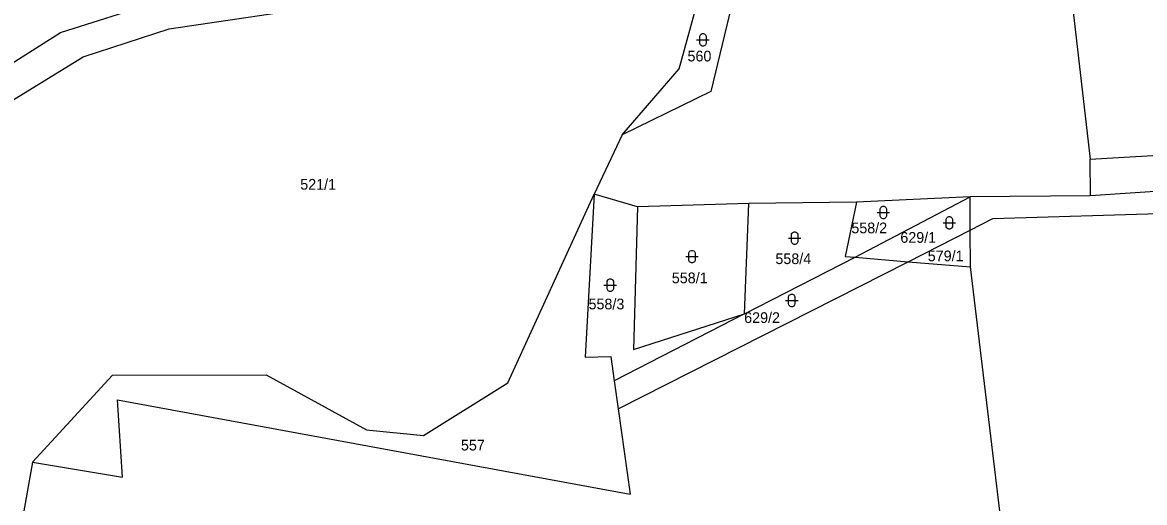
# Model space of a CAD drawing. Extents: x -794421 to -792735, y -1117671 to -1115559.
# Drawn here: x -793720 to -793541.7, y -1117244.8 to -1117168.6 of the extents above; entities that cross this region are included whole.
import ezdxf

# ---------------------------------------------------------------- set-up
doc = ezdxf.new("R2010")
doc.units = 0
for name, color, linetype in [('Vrstva 1', 7, 'Continuous'), ('Vrstva 14', 7, 'Continuous'), ('Vrstva 23', 7, 'Continuous')]:
    doc.layers.add(name, color=color, linetype=linetype)

msp = doc.modelspace()

# ---------------------------------------------------------------- linework, layer by layer
at = {"layer": 'Vrstva 1'}
for p, q in [((-793558.5, -1117120.1), (-793550.39, -1117190.25)), ((-793615.66, -1117175.93), (-793610.92, -1117158.67)), ((-793606.91, -1117164.01), (-793610.66, -1117179.49)), ((-793714, -1117170.15), (-793698.57, -1117165.26)), ((-793696.75, -1117169.55), (-793670.18, -1117165.64)), ((-793736.01, -1117184.09), (-793714, -1117170.15)), ((-793710.4, -1117173.99), (-793696.75, -1117169.55)), ((-793736.92, -1117190.31), (-793710.4, -1117173.99)), ((-793624.72, -1117186.38), (-793615.66, -1117175.93)), ((-793610.66, -1117179.49), (-793624.72, -1117186.38)), ((-793624.72, -1117186.38), (-793629.21, -1117195.83)), ((-793550.39, -1117190.25), (-793513.18, -1117188.14)), ((-793550.31, -1117196.07), (-793550.39, -1117190.25)), ((-793514.05, -1117193.72), (-793550.31, -1117196.07)), ((-793642.89, -1117225.74), (-793629.21, -1117195.83)), ((-793629.21, -1117195.83), (-793630.6, -1117221.67)), ((-793622.29, -1117197.82), (-793629.21, -1117195.83)), ((-793587.71, -1117205.83), (-793569.43, -1117196.25)), ((-793569.43, -1117196.25), (-793587.48, -1117197.06)), ((-793550.31, -1117196.07), (-793569.43, -1117196.25)), ((-793569.42, -1117201.52), (-793569.43, -1117196.25)), ((-793622.29, -1117197.82), (-793622.93, -1117220.47)), ((-793604.62, -1117197.29), (-793622.29, -1117197.82)), ((-793605.29, -1117214.83), (-793604.62, -1117197.29)), ((-793587.48, -1117197.06), (-793604.62, -1117197.29)), ((-793587.48, -1117197.06), (-793589.3, -1117205.7)), ((-793565.83, -1117199.7), (-793510.97, -1117198.02)), ((-793569.42, -1117201.52), (-793565.83, -1117199.7)), ((-793579.3, -1117206.53), (-793569.42, -1117201.52)), ((-793569.41, -1117207.36), (-793569.42, -1117201.52)), ((-793605.29, -1117214.83), (-793587.71, -1117205.83)), ((-793589.3, -1117205.7), (-793587.71, -1117205.83)), ((-793587.71, -1117205.83), (-793579.3, -1117206.53)), ((-793625.37, -1117229.91), (-793579.3, -1117206.53)), ((-793579.3, -1117206.53), (-793569.41, -1117207.36)), ((-793560.83, -1117278.35), (-793569.41, -1117207.36)), ((-793605.29, -1117214.83), (-793626.01, -1117225.43)), ((-793622.93, -1117220.47), (-793605.29, -1117214.83)), ((-793630.6, -1117221.67), (-793626.55, -1117221.59)), ((-793626.55, -1117221.59), (-793626.01, -1117225.43)), ((-793718.45, -1117238.37), (-793705.75, -1117224.56)), ((-793705.75, -1117224.56), (-793681.32, -1117224.51)), ((-793681.32, -1117224.51), (-793665.37, -1117233.24)), ((-793626.01, -1117225.43), (-793625.37, -1117229.91)), ((-793656.32, -1117234.1), (-793642.89, -1117225.74)), ((-793704.12, -1117240.73), (-793704.94, -1117228.48)), ((-793704.94, -1117228.48), (-793623.45, -1117243.42)), ((-793625.37, -1117229.91), (-793623.45, -1117243.42)), ((-793665.37, -1117233.24), (-793656.32, -1117234.1)), ((-793718.45, -1117238.37), (-793728.42, -1117294.94)), ((-793718.45, -1117238.37), (-793704.12, -1117240.73))]:
    msp.add_line(p, q, dxfattribs=at)
at = {"layer": 'Vrstva 23'}
for p, q in [((-793612.91, -1117171.31), (-793610.91, -1117171.31)), ((-793612.41, -1117170.71), (-793612.31, -1117170.51)), ((-793612.41, -1117171.91), (-793612.41, -1117170.71)), ((-793612.31, -1117172.11), (-793612.41, -1117171.91)), ((-793612.31, -1117170.51), (-793612.21, -1117170.41)), ((-793612.21, -1117170.41), (-793612.01, -1117170.31)), ((-793612.01, -1117170.31), (-793611.81, -1117170.31)), ((-793611.81, -1117170.31), (-793611.61, -1117170.41)), ((-793611.61, -1117170.41), (-793611.51, -1117170.51)), ((-793611.51, -1117170.51), (-793611.41, -1117170.71)), ((-793611.41, -1117171.91), (-793611.51, -1117172.11)), ((-793611.41, -1117170.71), (-793611.41, -1117171.91)), ((-793612.21, -1117172.21), (-793612.31, -1117172.11)), ((-793612.01, -1117172.31), (-793612.21, -1117172.21)), ((-793611.81, -1117172.31), (-793612.01, -1117172.31)), ((-793611.61, -1117172.21), (-793611.81, -1117172.31)), ((-793611.51, -1117172.11), (-793611.61, -1117172.21)), ((-793584.24, -1117198.72), (-793582.24, -1117198.72)), ((-793583.74, -1117198.12), (-793583.64, -1117197.92)), ((-793583.74, -1117199.32), (-793583.74, -1117198.12)), ((-793583.64, -1117197.92), (-793583.54, -1117197.82)), ((-793583.54, -1117197.82), (-793583.34, -1117197.72)), ((-793583.34, -1117197.72), (-793583.14, -1117197.72)), ((-793583.14, -1117197.72), (-793582.94, -1117197.82)), ((-793582.94, -1117197.82), (-793582.84, -1117197.92)), ((-793582.84, -1117197.92), (-793582.74, -1117198.12)), ((-793582.74, -1117198.12), (-793582.74, -1117199.32)), ((-793583.64, -1117199.52), (-793583.74, -1117199.32)), ((-793583.54, -1117199.62), (-793583.64, -1117199.52)), ((-793583.34, -1117199.72), (-793583.54, -1117199.62)), ((-793583.14, -1117199.72), (-793583.34, -1117199.72)), ((-793582.94, -1117199.62), (-793583.14, -1117199.72)), ((-793582.84, -1117199.52), (-793582.94, -1117199.62)), ((-793582.74, -1117199.32), (-793582.84, -1117199.52)), ((-793573.75, -1117200.38), (-793571.75, -1117200.38)), ((-793573.25, -1117199.78), (-793573.15, -1117199.58)), ((-793573.25, -1117200.98), (-793573.25, -1117199.78)), ((-793573.15, -1117199.58), (-793573.05, -1117199.48)), ((-793573.05, -1117199.48), (-793572.85, -1117199.38)), ((-793572.85, -1117199.38), (-793572.65, -1117199.38)), ((-793572.65, -1117199.38), (-793572.45, -1117199.48)), ((-793572.45, -1117199.48), (-793572.35, -1117199.58)), ((-793572.35, -1117199.58), (-793572.25, -1117199.78)), ((-793572.25, -1117199.78), (-793572.25, -1117200.98)), ((-793597.83, -1117202.18), (-793597.73, -1117201.98)), ((-793597.83, -1117203.38), (-793597.83, -1117202.18)), ((-793597.73, -1117201.98), (-793597.63, -1117201.88)), ((-793597.63, -1117201.88), (-793597.43, -1117201.78)), ((-793597.43, -1117201.78), (-793597.23, -1117201.78)), ((-793597.23, -1117201.78), (-793597.03, -1117201.88)), ((-793597.03, -1117201.88), (-793596.93, -1117201.98)), ((-793596.93, -1117201.98), (-793596.83, -1117202.18)), ((-793596.83, -1117202.18), (-793596.83, -1117203.38)), ((-793573.15, -1117201.18), (-793573.25, -1117200.98)), ((-793573.05, -1117201.28), (-793573.15, -1117201.18)), ((-793572.85, -1117201.38), (-793573.05, -1117201.28)), ((-793572.65, -1117201.38), (-793572.85, -1117201.38)), ((-793572.45, -1117201.28), (-793572.65, -1117201.38)), ((-793572.35, -1117201.18), (-793572.45, -1117201.28)), ((-793572.25, -1117200.98), (-793572.35, -1117201.18)), ((-793598.33, -1117202.78), (-793596.33, -1117202.78)), ((-793597.73, -1117203.58), (-793597.83, -1117203.38)), ((-793597.63, -1117203.68), (-793597.73, -1117203.58)), ((-793597.43, -1117203.78), (-793597.63, -1117203.68)), ((-793597.23, -1117203.78), (-793597.43, -1117203.78)), ((-793597.03, -1117203.68), (-793597.23, -1117203.78)), ((-793596.93, -1117203.58), (-793597.03, -1117203.68)), ((-793596.83, -1117203.38), (-793596.93, -1117203.58)), ((-793614.64, -1117205.73), (-793612.64, -1117205.73)), ((-793614.14, -1117205.13), (-793614.04, -1117204.93)), ((-793614.14, -1117206.33), (-793614.14, -1117205.13)), ((-793614.04, -1117204.93), (-793613.94, -1117204.83)), ((-793613.94, -1117204.83), (-793613.74, -1117204.73)), ((-793613.74, -1117204.73), (-793613.54, -1117204.73)), ((-793613.54, -1117204.73), (-793613.34, -1117204.83)), ((-793613.34, -1117204.83), (-793613.24, -1117204.93)), ((-793613.24, -1117204.93), (-793613.14, -1117205.13)), ((-793613.14, -1117205.13), (-793613.14, -1117206.33)), ((-793614.04, -1117206.53), (-793614.14, -1117206.33)), ((-793613.94, -1117206.63), (-793614.04, -1117206.53)), ((-793613.74, -1117206.73), (-793613.94, -1117206.63)), ((-793613.54, -1117206.73), (-793613.74, -1117206.73)), ((-793613.34, -1117206.63), (-793613.54, -1117206.73)), ((-793613.24, -1117206.53), (-793613.34, -1117206.63)), ((-793613.14, -1117206.33), (-793613.24, -1117206.53)), ((-793627.14, -1117209.64), (-793627.04, -1117209.44)), ((-793627.04, -1117209.44), (-793626.94, -1117209.34)), ((-793626.94, -1117209.34), (-793626.74, -1117209.24)), ((-793626.74, -1117209.24), (-793626.54, -1117209.24)), ((-793626.54, -1117209.24), (-793626.34, -1117209.34)), ((-793626.34, -1117209.34), (-793626.24, -1117209.44)), ((-793626.24, -1117209.44), (-793626.14, -1117209.64)), ((-793627.64, -1117210.24), (-793625.64, -1117210.24)), ((-793627.14, -1117210.84), (-793627.14, -1117209.64)), ((-793627.04, -1117211.04), (-793627.14, -1117210.84)), ((-793626.94, -1117211.14), (-793627.04, -1117211.04)), ((-793626.74, -1117211.24), (-793626.94, -1117211.14)), ((-793626.34, -1117211.14), (-793626.54, -1117211.24)), ((-793626.24, -1117211.04), (-793626.34, -1117211.14)), ((-793626.14, -1117210.84), (-793626.24, -1117211.04)), ((-793626.14, -1117209.64), (-793626.14, -1117210.84)), ((-793626.54, -1117211.24), (-793626.74, -1117211.24)), ((-793598.78, -1117212.67), (-793596.78, -1117212.67)), ((-793598.28, -1117212.07), (-793598.18, -1117211.87)), ((-793598.28, -1117213.27), (-793598.28, -1117212.07)), ((-793598.18, -1117211.87), (-793598.08, -1117211.77)), ((-793598.08, -1117211.77), (-793597.88, -1117211.67)), ((-793597.88, -1117211.67), (-793597.68, -1117211.67)), ((-793597.68, -1117211.67), (-793597.48, -1117211.77)), ((-793597.48, -1117211.77), (-793597.38, -1117211.87)), ((-793597.38, -1117211.87), (-793597.28, -1117212.07)), ((-793597.28, -1117212.07), (-793597.28, -1117213.27)), ((-793598.18, -1117213.47), (-793598.28, -1117213.27)), ((-793598.08, -1117213.57), (-793598.18, -1117213.47)), ((-793597.88, -1117213.67), (-793598.08, -1117213.57)), ((-793597.68, -1117213.67), (-793597.88, -1117213.67)), ((-793597.48, -1117213.57), (-793597.68, -1117213.67)), ((-793597.38, -1117213.47), (-793597.48, -1117213.57)), ((-793597.28, -1117213.27), (-793597.38, -1117213.47))]:
    msp.add_line(p, q, dxfattribs=at)

# ---------------------------------------------------------------- texts
at = {"layer": 'Vrstva 14'}
for s, p in [('560', (-793614.352, -1117174.74)), ('521/1', (-793675.893, -1117195.1)), ('558/2', (-793588.322, -1117202.02)), ('629/1', (-793580.533, -1117203.53)), ('558/4', (-793600.388, -1117206.91)), ('579/1', (-793576.176, -1117206.46)), ('558/1', (-793616.846, -1117209.95)), ('558/3', (-793630.082, -1117214.1)), ('629/2', (-793605.35, -1117216.26)), ('557', (-793650.356, -1117236.5))]:
    msp.add_text(s, height=1.7, dxfattribs=at).set_placement(p)

doc.saveas('drawing.dxf')
